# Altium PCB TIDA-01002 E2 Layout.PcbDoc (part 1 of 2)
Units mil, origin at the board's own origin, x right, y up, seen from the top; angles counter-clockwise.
Board outline 1055.12 x 1877.5 mil, 6 copper layers (Layer 1 - Top Layer, Layer 2 - GND, Layer 3 - Signal, Layer 4 - Signal 2, Layer 5 - GND, Layer 6 - Bottom Layer), stack 61.268 mil thick; 83 components, 52 nets, 333 pads, 146 vias.
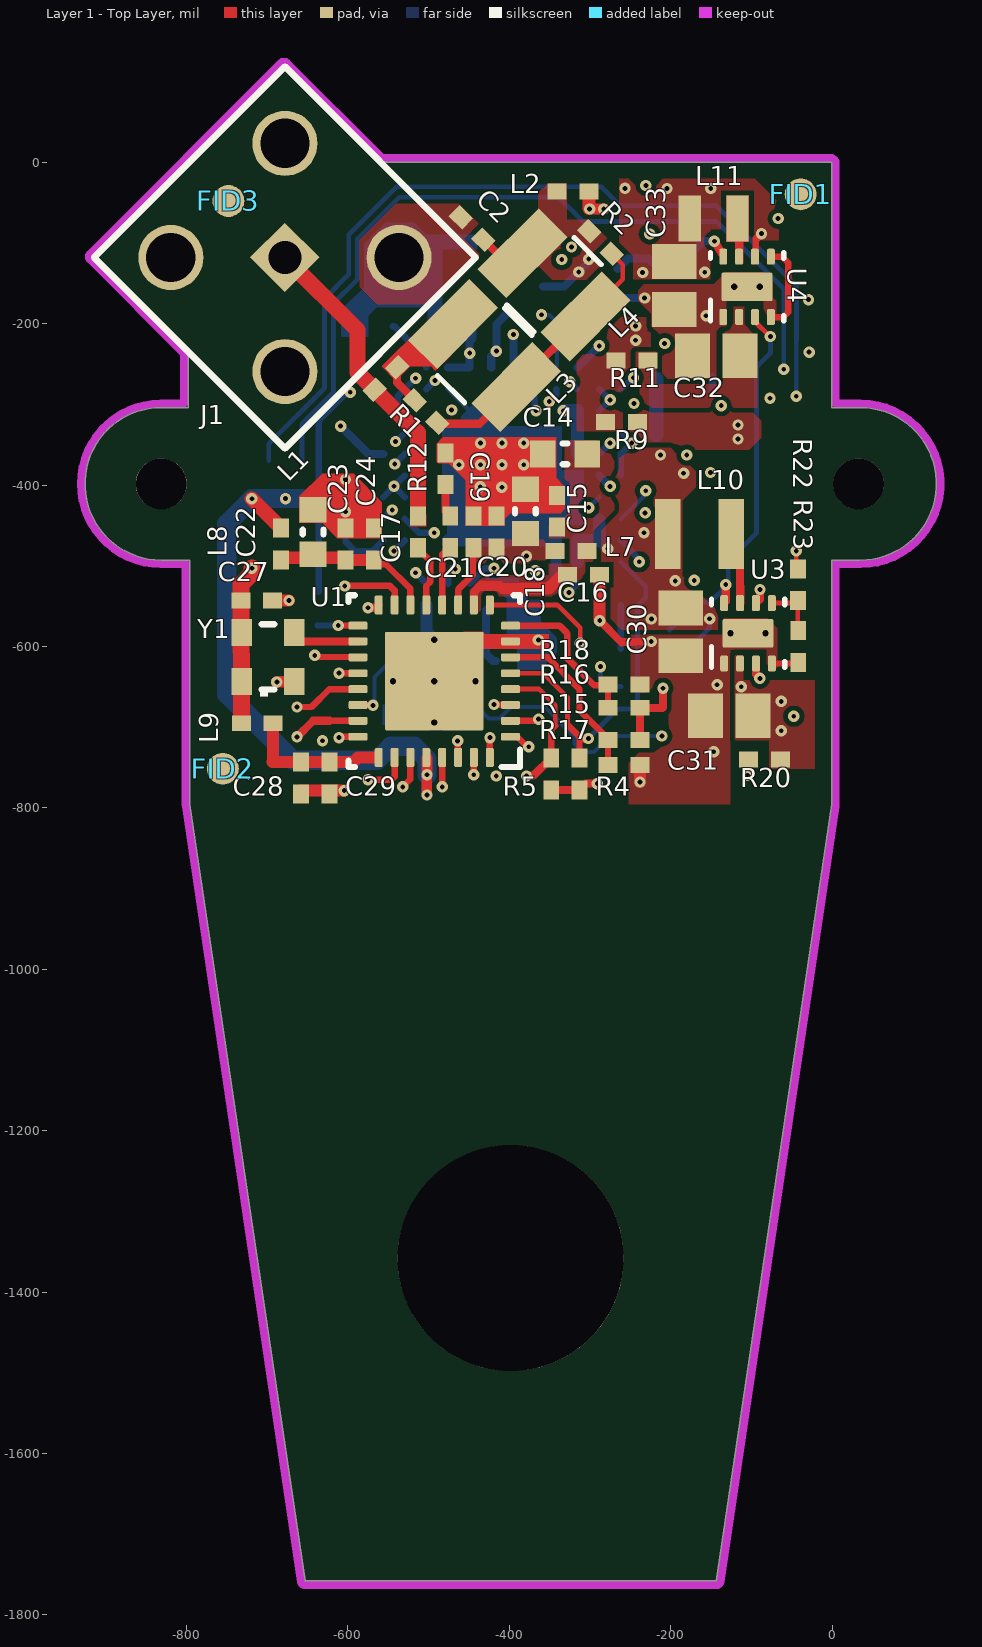
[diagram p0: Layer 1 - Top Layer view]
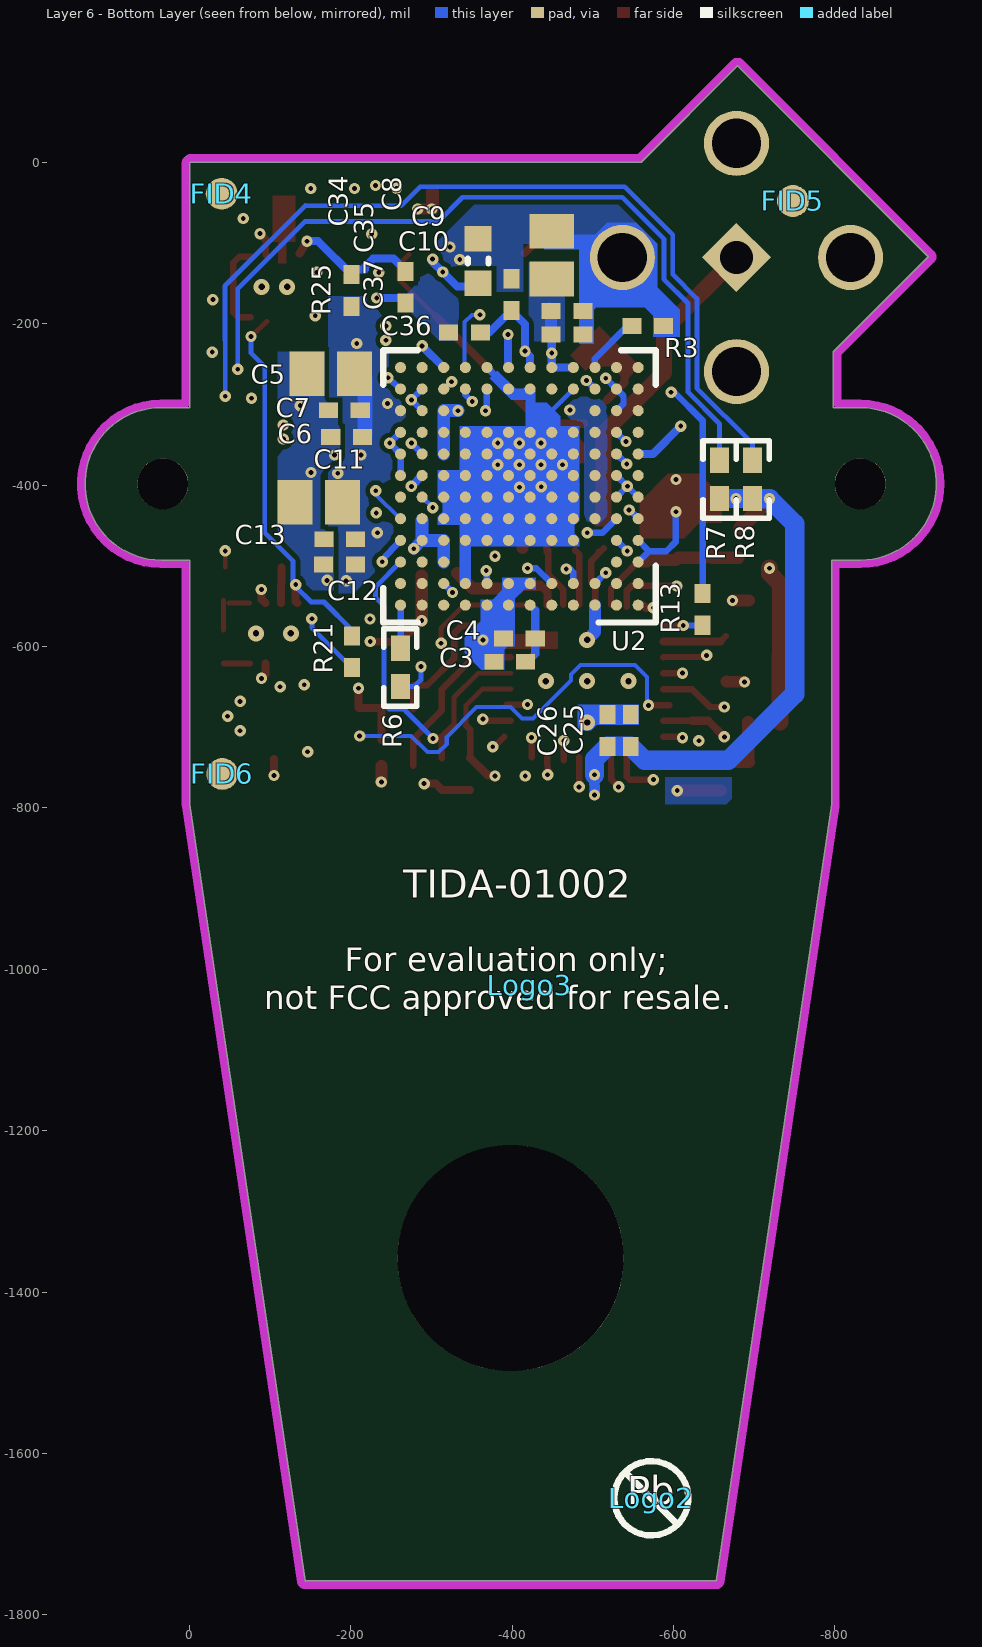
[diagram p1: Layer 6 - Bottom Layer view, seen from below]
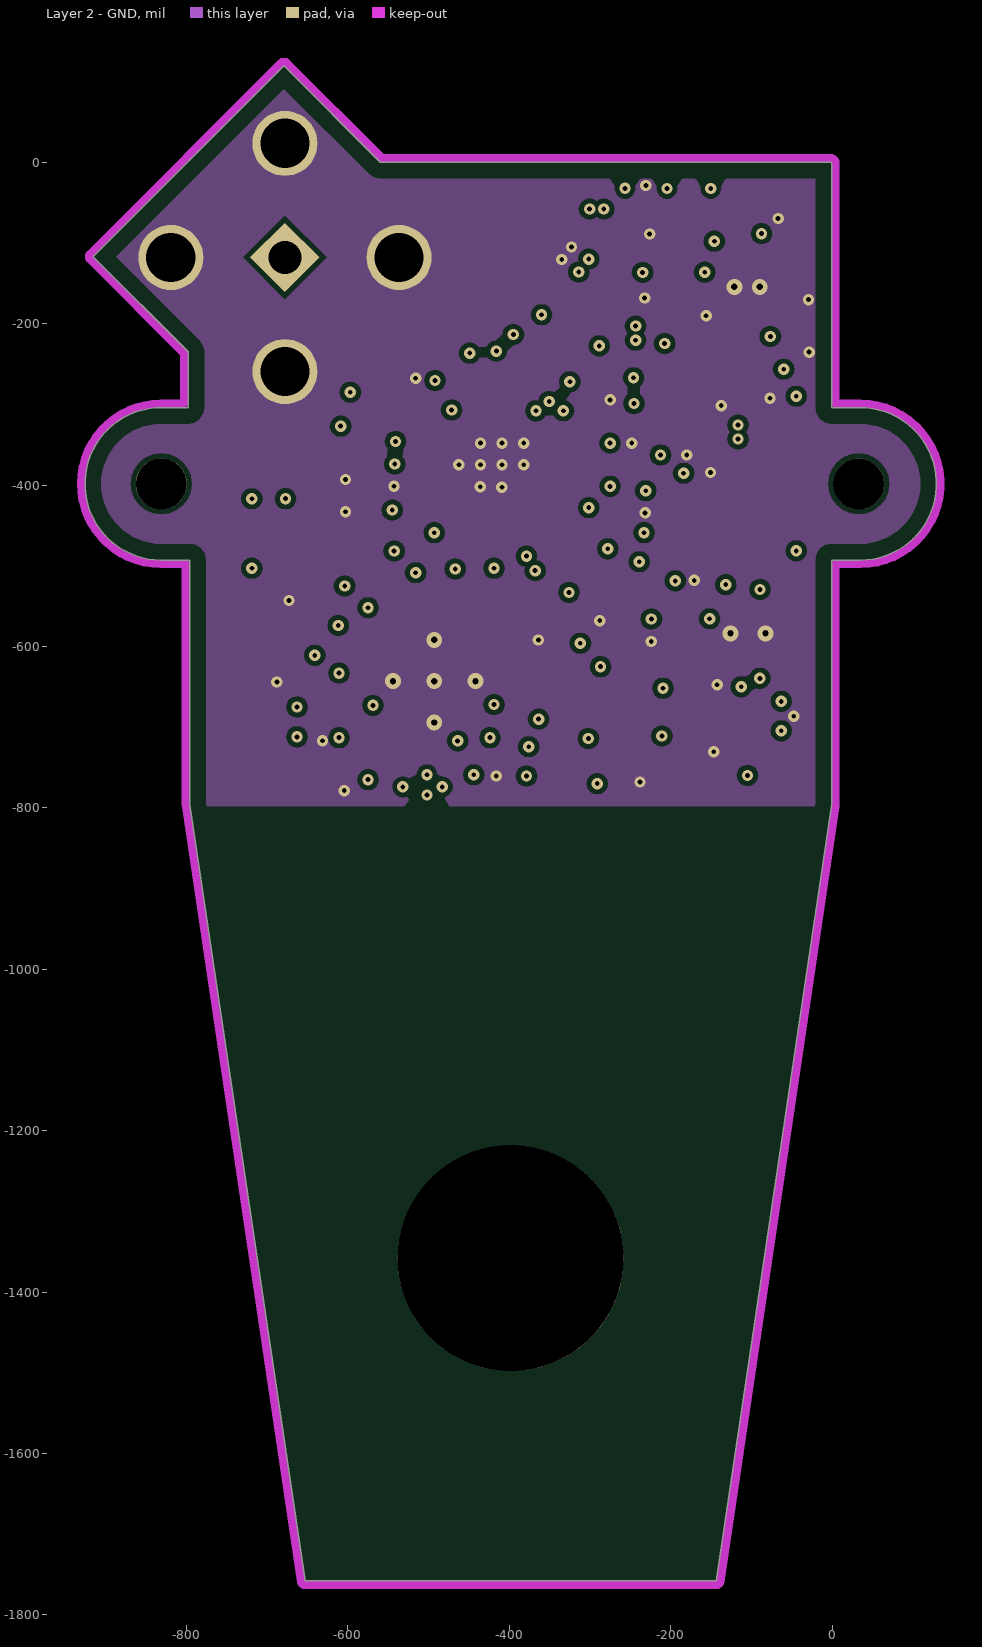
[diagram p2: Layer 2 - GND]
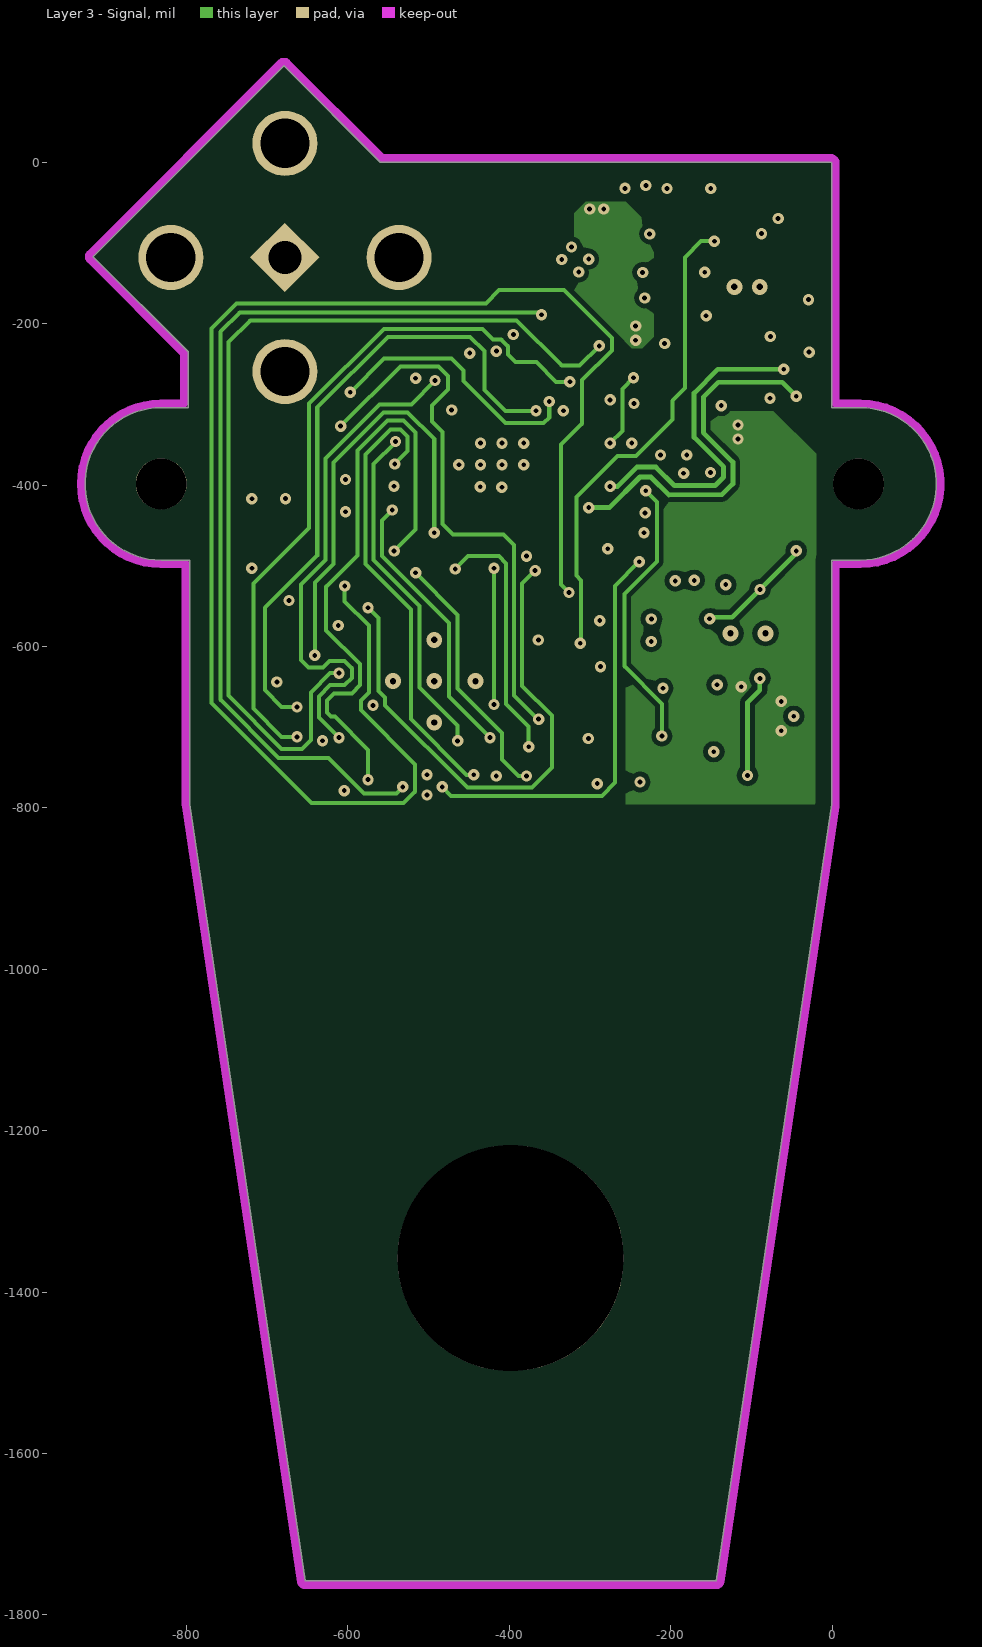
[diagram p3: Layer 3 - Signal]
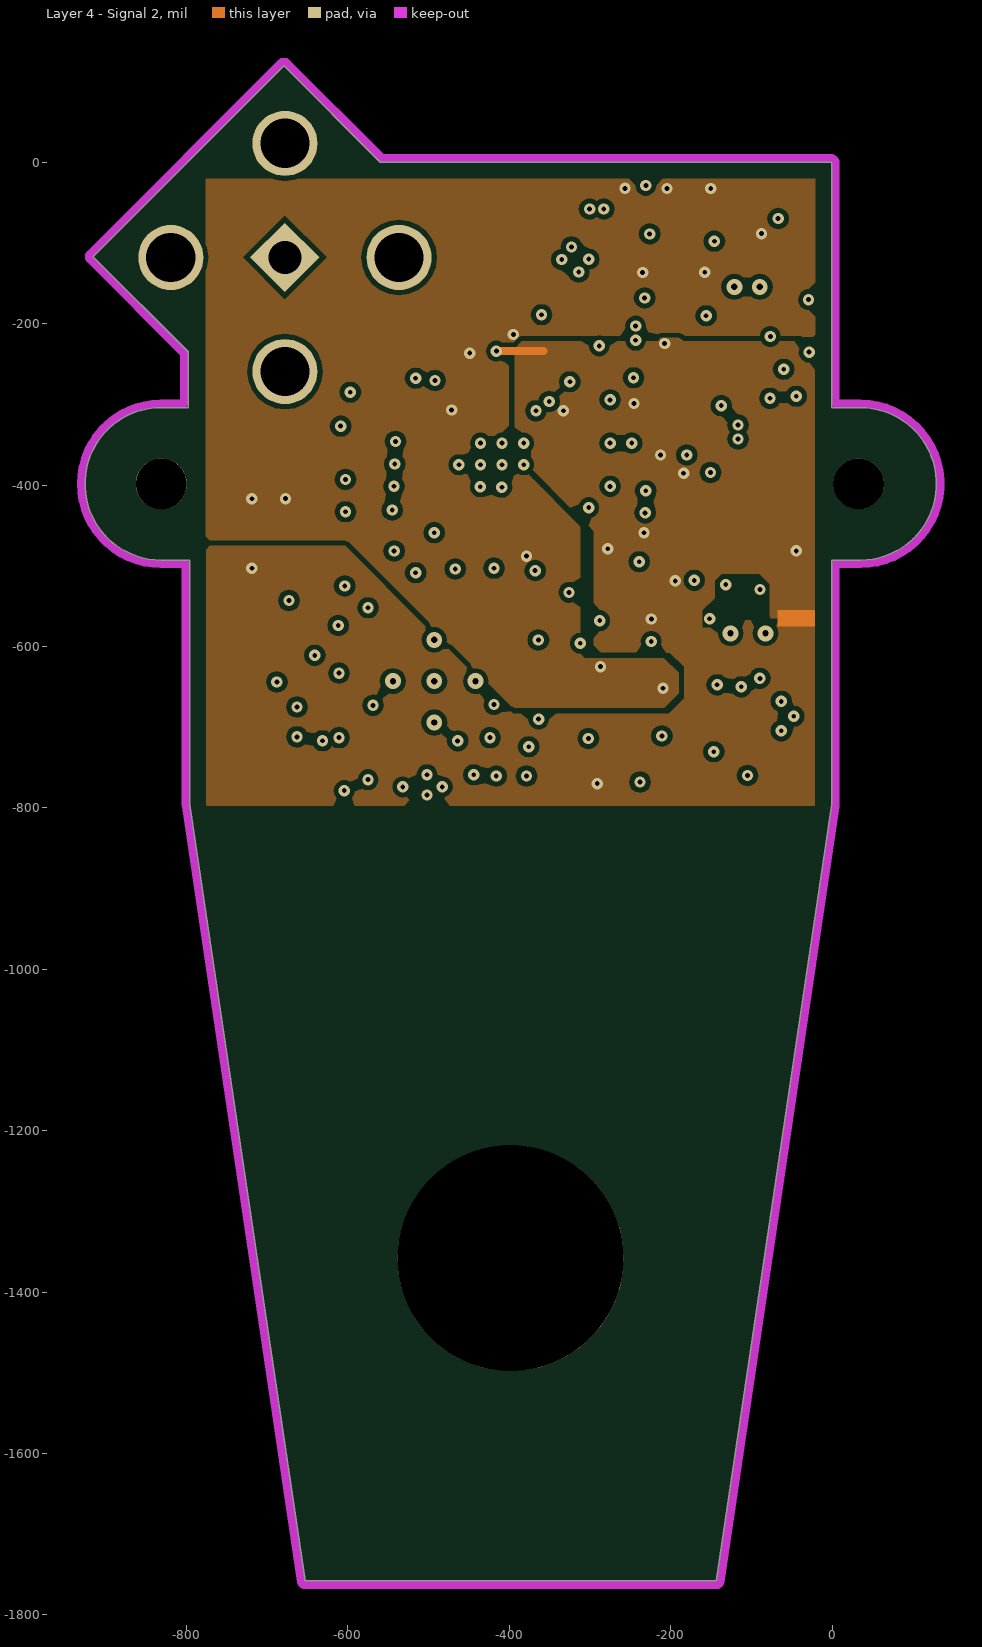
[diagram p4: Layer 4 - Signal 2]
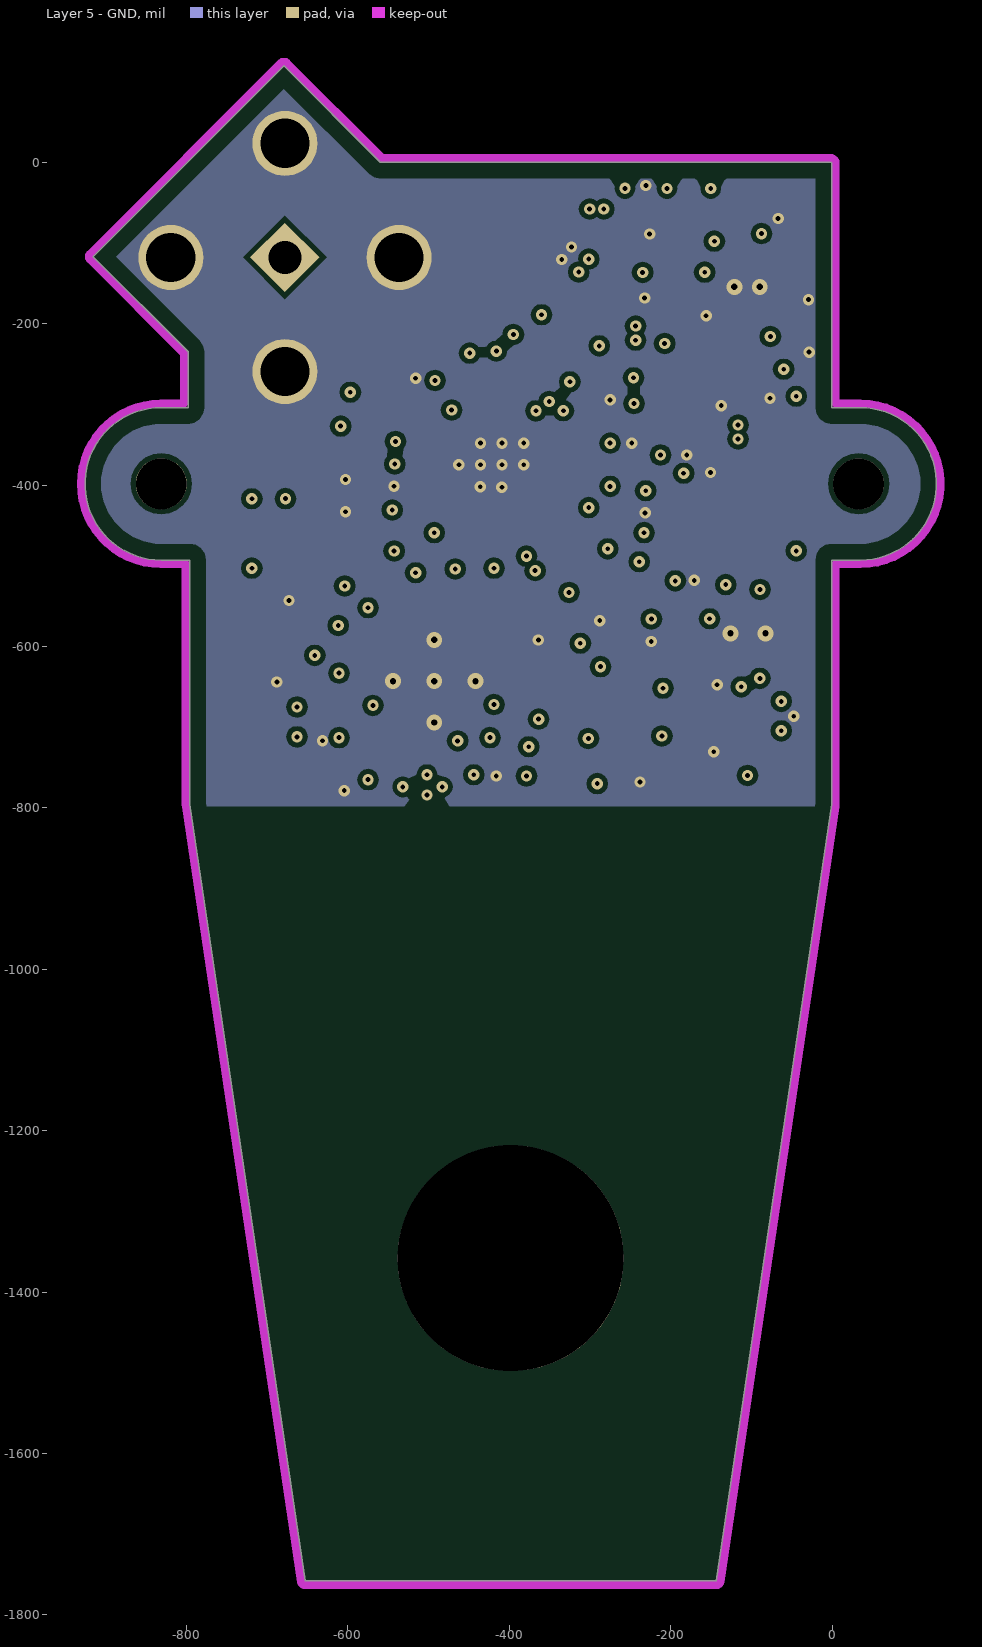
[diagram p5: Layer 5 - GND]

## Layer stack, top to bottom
Top Solder: solder mask 0.4, Solder Resist, Dk 3.5
Layer 1 - Top Layer: signal copper 1.4
Dielectric 1: core 10.6, 370HR, Dk 4.2
Layer 2 - GND: signal copper 1.417
Dielectric 6: prepreg 8, 370HR, Dk 4.2
Layer 3 - Signal: signal copper 1.417
Dielectric 3: core 15.6, 370HR, Dk 4.2
Layer 4 - Signal 2: signal copper 1.417
Dielectric 4: prepreg 8, 370HR, Dk 4.2
Layer 5 - GND: signal copper 1.417
Dielectric 5: core 10.6, 370HR, Dk 4.2
Layer 6 - Bottom Layer: signal copper 1.4
Bottom Solder: solder mask 0.4, Solder Resist, Dk 3.5

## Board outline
-831.32,-492.99 -795.89,-492.99 -795.89,-796.14 -795.89,-795.5 -653,-1758 -143.5,-1758 -0.61,-795.5 -0.61,-796.14 -0.61,-492.99 34.82,-492.99 ccw(c34.82,-398.5) 34.82,-304.01 -0.61,-304.01 -0.61,-0.86 -1.61,0.13 -559.88,0.13 -679.25,119.5 -915.75,-117 -797.88,-234.87 -797.88,-304.01 -831.32,-304.01 ccw(c-831.32,-398.5)

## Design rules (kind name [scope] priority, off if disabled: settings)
AcuteAngle [All] p1: minimum=4.50000000000000E+0001 checktracksonly=FALSE
AssemblyTestPointUsage [All] p1: valid=2
BoardOutlineClearance BoardOutlineClearance_MountingHoles [OnCopper and InComponentClass('Mounting Holes')] p1: gap=40 ignorepadtopadclearanceinfootprint=FALSE
BoardOutlineClearance BoardOutlineClearance_Poly [OnCopper and InPoly] p2: gap=19 ignorepadtopadclearanceinfootprint=FALSE
BoardOutlineClearance [OnCopper and Not InComponentClass('Logo') and not InComponentClass('FiducialMark') and not InRegion(1000,500,4000,800)] p3: gap=20 ignorepadtopadclearanceinfootprint=FALSE
Clearance Clearance_Keepouts [((IsTrack Or IsArc) And Not InPoly) And IsFree and IsKeepOut vs ((IsTrack Or IsArc) And Not InPoly) And IsFree and IsKeepOut] p1: gap=5 ignorepadtopadclearanceinfootprint=FALSE except(0: Arc-Hole Track-Hole SMDPad-Hole THPad-Hole Via-Hole Fill-Hole Poly-Hole Region-Hole Text-Hole)
Clearance Clearance_Poly [InPolygon] p2: gap=6 ignorepadtopadclearanceinfootprint=FALSE except(0: Arc-Hole Track-Hole SMDPad-Hole THPad-Hole Via-Hole Fill-Hole Poly-Hole Region-Hole Text-Hole)
Clearance [All] p3: gap=5 ignorepadtopadclearanceinfootprint=FALSE except(0: Arc-Hole Track-Hole SMDPad-Hole THPad-Hole Via-Hole Fill-Hole Poly-Hole Region-Hole Text-Hole)
ComponentClearance ComponentClearance_U4-FID1 [InComponent('U4') vs InComponent('FID1')] p1: gap=0 collisioncheckmode=3 verticalgap=0 showdistances=FALSE
ComponentClearance ComponentClearance_J1-FID3 [InComponent('J1') vs InComponent('FID3')] p2: gap=0 collisioncheckmode=3 verticalgap=0 showdistances=FALSE
ComponentClearance ComponentClearance_MountingHoles_FiducialMarks [InComponentClass('Mounting Holes') vs InComponentClass('FiducialMark')] p3: gap=5 collisioncheckmode=3 verticalgap=10 showdistances=FALSE
ComponentClearance ComponentClearance_Shunt [InComponentClass('Header') vs InComponentClass('Shunt')] p4: gap=0 collisioncheckmode=3 verticalgap=0 showdistances=FALSE
ComponentClearance ComponentClearance_Logo [InComponentClass('Logo')] p5: gap=5 collisioncheckmode=3 verticalgap=10 showdistances=FALSE
ComponentClearance ComponentClearance_ScrewToNut [(HasFootprint('NY PMS 440 0025 PH')) vs (HasFootprint('Keystone_1902C'))] p6: gap=5 collisioncheckmode=3 verticalgap=10 showdistances=FALSE
ComponentClearance ComponentClearance_MountingHoles [InComponentClass('Mounting Holes')] p7: gap=5 collisioncheckmode=3 verticalgap=100000 showdistances=FALSE
ComponentClearance ComponentClearance_SmallPassives [HasFootprint('0201*') or HasFootprint('0402*') or HasFootprint('0508') or HasFootprint('0603*') or HasFootprint('0612') or HasFootprint('0805*') or HasFootprint('0815*') or HasFootprint('0830*') or HasFootprint('1206*') or HasFootprint('1210*') or HasFootprint('1808*') or HasFootprint('1812*') or HasFootprint('1825*') or HasFootprint('2010*') or HasFootprint('2220*') or HasFootprint('2225*') or HasFootprint('2512*') or HasFootprint('2728*') or HasFootprint('3518*') vs HasFootprint('0201*') or HasFootprint('0402*') or HasFootprint('0508') or HasFootprint('0603*') or HasFootprint('0612') or HasFootprint('0805*') or HasFootprint('0815*') or HasFootprint('0830*') or HasFootprint('1206*') or HasFootprint('1210*') or HasFootprint('1808*') or HasFootprint('1812*') or HasFootprint('1825*') or HasFootprint('2010*') or HasFootprint('2220*') or HasFootprint('2225*') or HasFootprint('2512*') or HasFootprint('2728*') or HasFootprint('3518*')] p8: gap=5 collisioncheckmode=3 verticalgap=10 showdistances=FALSE
ComponentClearance ComponentClearance_THtoSMT [IsThruComponent vs IsSMTComponent] p9: gap=5 collisioncheckmode=3 verticalgap=30 showdistances=FALSE
ComponentClearance ComponentClearance_THtoTH [IsThruComponent vs IsThruComponent] p10: gap=5 collisioncheckmode=3 verticalgap=30 showdistances=FALSE
ComponentClearance [All] p11: gap=5 collisioncheckmode=3 verticalgap=10 showdistances=FALSE
DiffPairsRouting [All] p1: maxlimit=100 minlimit=10 mostfreqgap=10 toplayer_minwidth=15 toplayer_maxwidth=15 toplayer_prefwidth=15 midlayer1_minwidth=15 midlayer1_maxwidth=15 midlayer1_prefwidth=15 midlayer2_minwidth=15 midlayer2_maxwidth=15 midlayer2_prefwidth=15 midlayer3_minwidth=15 midlayer3_maxwidth=15 midlayer3_prefwidth=15 midlayer4_minwidth=15 midlayer4_maxwidth=15 midlayer4_prefwidth=15 bottomlayer_minwidth=15 bottomlayer_maxwidth=15 bottomlayer_prefwidth=15 maxuncoupledlength=1000
FabricationTestPointUsage TestPointUsage [All] p1: valid=2 allowmultiple=FALSE
FabricationTestpoint Testpoint [All] p1: side=3 testpointundercomponent=TRUE minsize=40 maxsize=100 preferedsize=60 minholesize=0 maxholesize=40 preferedholesize=32 testpointgrid=1 allowsidetop=TRUE allowsidebottom=TRUE usegrid=TRUE gridtolerance=0.01
FanoutControl Fanout_LCC [IsLCC] p1: bgadir=Out bgaviamode=Centered fanoutstyle=Auto fanoutdirection=Alternating viagrid=1 // Fanout_LCC (Default Rule)
FanoutControl Fanout_BGA [IsBGA] p2: bgadir=Out bgaviamode=Centered fanoutstyle=Auto fanoutdirection=Alternating viagrid=1 // Fanout_BGA (Default Rule)
FanoutControl Fanout_Default [All] p4: bgadir=Out bgaviamode=Centered fanoutstyle=Auto fanoutdirection=Alternating viagrid=1 // Fanout_Default (Default Rule)
FanoutControl Fanout_Small [(CompPinCount < 5)] p5: bgadir=Out bgaviamode=Centered fanoutstyle=Auto fanoutdirection=OutThenIn viagrid=1 // Fanout_Small (Default Rule)
HoleSize [All] p1: absolutevalues=TRUE maxlimit=280 minlimit=6 maxpercent=80.000 minpercent=20.000
MinimumAnnularRing MinimumAnnularRing_ThermalPadVias [IsVia and InAnyComponent] p1: minimumring=5.91
MinimumAnnularRing [All] p2: minimumring=4
MinimumSolderMaskSliver MinimumSolderMaskSliver_Logo [InComponentClass('Logo') vs InComponentClass('Logo')] p1: minsoldermaskwidth=0.7
MinimumSolderMaskSliver [All] p2: minsoldermaskwidth=3.94
PlaneConnect [All] p1: planeconnectstyle=Relief reliefexpansion=10 reliefentries=4 reliefconductorwidth=10 reliefairgap=10
PolygonConnect [All] p1: connectstyle=Direct reliefconductorwidth=10 reliefentries=4 polygonreliefangle="90 Angle" airgapwidth=10
RoutingVias ThermalPadVias [IsVia and InAnyComponent] p1: holewidth=7.87 width=19.68 viastyle="Through Hole" minholewidth=7.87 minwidth=19.68 maxholewidth=12.99 maxwidth=23.62
RoutingVias [All] p2: holewidth=16 width=34 viastyle="Through Hole" minholewidth=6 minwidth=14 maxholewidth=40 maxwidth=65
SilkToBoardRegionClearance [Not ((IsComment or IsDesignator) And (Hide <> 'False')) and not InRegion(1000,500,4000,800)] p1:
SilkToSilkClearance SilkToSilkClearance_Pb-FreeLogo [(HasFootprint('Pb-Free_Overlay_Medium') OR HasFootprint('Pb-Free_Overlay_Small')) vs (HasFootprint('Pb-Free_Overlay_Medium') OR HasFootprint('Pb-Free_Overlay_Small'))] p1: silktosilkclearance=0
SilkToSilkClearance [All] p2: silktosilkclearance=3
SilkToSolderMaskClearance SilkToComponentPadClearance [IsPad and InAnycomponent] p1: minsilkscreentomaskgap=3 clearancetoexposedcopper=TRUE
SilkToSolderMaskClearance "Silk to Solder Mask Opening" [All] p2: minsilkscreentomaskgap=3 clearancetoexposedcopper=FALSE
SolderMaskExpansion [All] p1: expansion=1.97
Width [All] p1: maxlimit=100 minlimit=5 preferedwidth=10 checkconnectedcopper=TRUE
15 further rules are at their usual default settings.

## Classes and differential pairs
component class Serializer: C14 C15 C16 C17 C18 C19 C20 C21 C22 C23 C24 C25 C26 C27 C28 C29 C37 L7 L8 L9 R12 R13 R15 R16 R17 R18 R25 U1 Y1
component class "Power over Coax Filter & Power Supply": C2 C30 C31 C32 C33 C34 J1 L1 L2 L3 L4 L10 L11 R1 R2 R9 R11 R20 R21 R22 R23 U3 U4
component class "ON Semiconductor AS0140AT Imager + ISP": C3 C4 C5 C6 C7 C8 C9 C10 C11 C12 C13 C35 C36 R3 R4 R5 R6 R7 R8 U2
component class AssemblyNote: ZZ1 ZZ2 ZZ3
component class FiducialMark: FID1 FID2 FID3 FID4 FID5 FID6
component class TID_Hardware: FID1 FID2 FID3 FID4 FID5 FID6 Logo2 Logo3 ZZ1 ZZ2 ZZ3

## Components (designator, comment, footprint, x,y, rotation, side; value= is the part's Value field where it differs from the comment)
C2 "C1005X7R1E104K050BB" 0402L -446,-82 r135 top value=0.1µF
C3 "GRM155R61A105KE15D" 0402L -397,-619 r0 bottom value=1uF
C4 "GRM155R71C104KA88D" 0402L -409,-590 r0 bottom value=0.1uF
C5 "GRM21BR71A106KE51L" 0805L -175.3,-261.9 r0 bottom value=10uF
C6 "C1005X7R1E104K050BB" 0402L -194.9,-340.3 r0 bottom value=0.1µF
C7 "GRM155R71C103KA01D" 0402L -192.1,-307.3 r0 bottom value=0.01uF
C8 "GRM21BR71A106KE51L" 0805L -449,-115 r90 bottom value=10uF
C9 "C1005X7R1E104K050BB" 0402L -468,-184.5 r180 bottom value=0.1µF
C10 "GRM155R71C103KA01D" 0402L -468,-213.5 r180 bottom value=0.01uF
C11 "GRM21BR71A106KE51L" 0805L -160.3,-421.1 r0 bottom value=10uF
C12 "GRM155R61A105KE15D" 0402L -186.1,-498.2 r0 bottom value=1uF
C13 "GRM155R71C103KA01D" 0402L -186.4,-467.1 r0 bottom value=0.01uF
C14 "JMK107BB7475MA-T" 0603L -331,-361.26 r180 top value=4.7uF
C15 "GRM155R71C104KA88D" 0402L -341,-432.5 r90 top value=0.1uF
C16 "GRM155R71C103KA01D" 0402L -308,-511.1 r0 top value=0.01uF
C17 "C1005X7R1H104K" 0402L -513,-458 r270 top value=0.1uF
C18 "CL10B475KQ8NQNC" 0603L -380.1,-432.5 r90 top value=4.7µF
C19 "GRM155R71C104KA88D" 0402L -444.6,-458 r90 top value=0.1uF
C20 "GRM155R71C103KA01D" 0402L -416,-458.1 r90 top value=0.01uF
C21 "C1005X7R1H104K" 0402L -473.2,-458 r270 top value=0.1uF
C22 "CL10B475KQ8NQNC" 0603L -643,-458 r90 top value=4.7µF
C23 "GRM155R71C104KA88D" 0402L -603,-473 r90 top value=0.1uF
C24 "GRM155R71C103KA01D" 0402L -568,-473 r90 top value=0.01uF
C25 "GRM155R71C104KA88D" 0402L -547,-704 r90 bottom value=0.1uF
C26 "GRM155R71C103KA01D" 0402L -518,-704 r90 bottom value=0.01uF
C27 "GRM155R71C104KA88D" 0402L -713,-543 r0 top value=0.1uF
C28 "GRM155R71C104KA88D" 0402L -658,-763 r270 top value=0.1uF
C29 "GRM155R71C103KA01D" 0402L -623,-763 r270 top value=0.01uF
C30 "GRM21BR71A106KE51L" 0805L -187.4,-582 r270 top value=10uF
C31 "CL21B106KOQNNNE" 0805L -127.5,-686 r180 top value=10uF
C32 "CL21B106KOQNNNE" 0805L -143.73,-240.03 r180 top value=10uF
C33 "GRM21BR71A106KE51L" 0805L -195.6,-152.7 r270 top value=10uF
C34 "GRM188Z71C475KE21D" 0603L -358,-122.5 r90 bottom value=4.7uF
C35 "GRM155R61A105KE15D" 0402L -399,-164 r90 bottom value=1uF
C36 "C1005X7R1E104K050BB" 0402L -341,-211 r0 bottom value=0.1µF
C37 "GRM155R71C104KA88D" 0402L -268.1,-154.9 r270 bottom value=0.1uF
FID1 "Fiducial" Fiducial10-20 -39.1,-39.8 r180 top
FID2 "Fiducial" Fiducial10-20 -754.9,-751.4 r0 top
FID3 "Fiducial" Fiducial10-20 -748,-48 r0 top
FID4 "Fiducial" Fiducial10-20 -40,-39 r0 bottom
FID5 "Fiducial" Fiducial10-20 -748,-48 r0 bottom
FID6 "Fiducial" Fiducial10-20 -41,-758 r0 bottom
J1 "59S10H-40ML5-Z" Rosenberger_59S10H-40ML5-Z -678,-118 r225 top locked
L1 "BLM15AX102SN1D" 0402L -553,-268 r45 top value="1000 ohm"
L2 "BLM15AX102SN1D" 0402L -321,-36 r0 top value="1000 ohm"
L3 "CBC3225T4R7MR" CBC3225 -430.5,-239.5 r315 top value=4.7uH
L4 "CBC3225T101MR" CBC3225 -344.6,-151.8 r135 top value=100uH
L7 "BLM15AX102SN1D" 0402L -323.5,-481.9 r0 top value="1000 ohm"
L8 "BLM15AX102SN1D" 0402L -683,-473 r270 top value="1000 ohm"
L9 "BLM15AX102SN1D" 0402L -712.3,-695.1 r0 top value="1000 ohm"
L10 "74479887310A" WE-PMI_1008 -164.5,-460.5 r180 top value=10uH
L11 "74479775222" WE-PMI-0805_1 -146.9,-69.9 r180 top value=2.2uH
Logo2 "Pb-Free Symbol" Pb-Free_Overlay_Small -572.5,-1655.5 r180 bottom
Logo3 "FCC disclaimer" FCC_disclaimer_stacked -422,-1019.5 r180 bottom
R1 "CRCW04022K00FKED" 0402L -503,-309 r135 top value=2.00k
R2 "CRCW04022K00FKED" 0402L -287,-99.5 r315 top value=2.00k
R3 "CRCW040210K0JNED" 0402L -568,-203 r0 bottom value=10k
R4 "CRCW04023K30JNED" 0402L -313,-758 r270 top value=3.3k
R5 "CRCW04023K30JNED" 0402L -348,-758 r270 top value=3.3k
R6 "CRCW040210K0JNED" 0402 -261.5,-626 r270 bottom value=10k
R7 "CRCW04023K30JNED" 0402 -657,-393 r270 bottom value=3.3k
R8 "CRCW04023K30JNED" 0402 -698,-393 r270 bottom value=3.3k
R9 "CRCW04020000Z0ED" 0402L -261,-322 r180 top value=0
R11 "CRCW04020000Z0ED" 0402L -248,-245.5 r180 top value=0
R12 "CRCW040249R9FKED" 0402L -479,-379.8 r90 top value=49.9
R13 "CRCW040233R0JNED" 0402L -636,-554 r90 bottom value=33
R15 "CRCW040210K0JNED" 0402L -258,-716 r0 top value=10k
R16 "CRCW040210K0JNED" 0402L -258,-676 r0 top value=10k
R17 "CRCW04020000Z0ED" 0402L -258,-747 r180 top value=0
R18 "CRG0402F4K7" 0402L -258,-647 r180 top value=4.70k
R20 "CRCW040210K0JNED" 0402L -83.7,-740.2 r180 top value=10k
R21 "CRCW0402100KFKED" 0402L -201.5,-606.5 r270 bottom value=100k
R22 "CRCW040282K5FKED" 0402L -42.5,-523.5 r90 top value=82.5k
R23 "CRCW040233K2FKED" 0402L -42,-600 r90 top value=33.2k
R25 "CRCW0402100KFKED" 0402L -200.9,-158.8 r270 bottom value=100k
U1 "DS90UB913ATRTVTQ1" RTV0032A -493,-643 r180 top locked
U2 "ON Semiconductor AS0140AT" BGA130_850x850x162 -408.96,-401.54 r0 bottom locked
U3 "TPS62170QDSGRQ1" DSG0008A#1 -104.2,-583.7 r90 top
U4 "TPS62171QDSGRQ1" DSG0008A#2 -105.4,-154.4 r90 top
Y1 "ASDMB-48.000MHZ-LY-T" Abracon_ASDMB -699,-613 r90 top
ZZ1 "These assemblies are ESD sensitive, ESD precautions shall be observed." AssemblyNote -738,2071.11 r0 top
ZZ2 "These assemblies must be clean and free from flux and all contaminants. Use of no clean flux is not acceptable." AssemblyNote -738,1982.56 r0 top
ZZ3 "These assemblies must comply with workmanship standards IPC-A-610 Class 2, unless otherwise specified." AssemblyNote -738,1894 r0 top

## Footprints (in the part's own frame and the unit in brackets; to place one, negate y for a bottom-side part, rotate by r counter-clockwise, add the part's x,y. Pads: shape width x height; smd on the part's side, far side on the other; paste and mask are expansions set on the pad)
0402 [mm] "0402 from SM-752 data"
  rect 0.8x0.6 smd: 1(-0.6,0) 2(0.6,0)
  silkscreen extent -1.22,-0.52 1.22,0.52, body extent -0.55,-0.3 0.55,0.3, height 0.6
0402L [mm] "0402 from SM-752 data"
  rect 0.6x0.5 smd: 1(-0.5,0) 2(0.5,0)
  body extent -0.55,-0.3 0.55,0.3, height 0.6
0603L [mm] "0603 from SM-752 data"
  rect 0.8x0.85 smd: 1(-0.7,0) 2(0.7,0)
  silkscreen extent -0.07,-0.33 0.07,0.33, body extent -0.87,-0.47 0.87,0.47, height 1
0805L [mm] "0805 from SM-752 data"
  rect 1.1x1.4 smd: 1(-0.75,0) 2(0.75,0)
  body extent -1.1,-0.72 1.1,0.72, height 1.45
Abracon_ASDMB [mm] "SMD, 4-Leads, Body 2.5x2mm"
  rect 0.85x0.65 smd: 1(-0.775,0.825) 2(-0.775,-0.825) 3(0.775,-0.825) 4(0.775,0.825)
  silkscreen extent -1.25,-0.2 1.02,0.25, body extent -1.02,-1.27 1.02,1.28, height 0.91
AssemblyNote [mil] "Assembly Note"
BGA130_850x850x162 [mm] "BGA, 130-Balls, Body 8.5x8.5mmx1.62mm, Pitch 0.68mm"
  round 0.35 smd: A1(-3.74,3.74) A2(-3.06,3.74) A3(-2.38,3.74) A4(-1.7,3.74) A5(-1.02,3.74) A6(-0.34,3.74) A7(0.34,3.74) A8(1.02,3.74) A9(1.7,3.74) A10(2.38,3.74) A11(3.06,3.74) A12(3.74,3.74) B1(-3.74,3.06) B2(-3.06,3.06) B3(-2.38,3.06) B4(-1.7,3.06) B5(-1.02,3.06) B6(-0.34,3.06) B7(0.34,3.06) B8(1.02,3.06) B9(1.7,3.06) B10(2.38,3.06) B11(3.06,3.06) B12(3.74,3.06) C1(-3.74,2.38) C2(-3.06,2.38) C10(2.38,2.38) C11(3.06,2.38) C12(3.74,2.38) D1(-3.74,1.7) D2(-3.06,1.7) D4(-1.7,1.7) D5(-1.02,1.7) D6(-0.34,1.7) D7(0.34,1.7) D8(1.02,1.7) D9(1.7,1.7) D10(2.38,1.7) D11(3.06,1.7) D12(3.74,1.7) E1(-3.74,1.02) E2(-3.06,1.02) E3(-2.38,1.02) E4(-1.7,1.02) E5(-1.02,1.02) E6(-0.34,1.02) E7(0.34,1.02) E8(1.02,1.02) E9(1.7,1.02) E10(2.38,1.02) E11(3.06,1.02) E12(3.74,1.02) F1(-3.74,0.34) F2(-3.06,0.34) F3(-2.38,0.34) F4(-1.7,0.34) F5(-1.02,0.34) F6(-0.34,0.34) F7(0.34,0.34) F8(1.02,0.34) F9(1.7,0.34) F10(2.38,0.34) F11(3.06,0.34) F12(3.74,0.34) G1(-3.74,-0.34) G2(-3.06,-0.34) G3(-2.38,-0.34) G4(-1.7,-0.34) G5(-1.02,-0.34) G6(-0.34,-0.34) G7(0.34,-0.34) G8(1.02,-0.34) G9(1.7,-0.34) G10(2.38,-0.34) G11(3.06,-0.34) G12(3.74,-0.34) H1(-3.74,-1.02) H2(-3.06,-1.02) H3(-2.38,-1.02) H4(-1.7,-1.02) H5(-1.02,-1.02) H6(-0.34,-1.02) H7(0.34,-1.02) H8(1.02,-1.02) H9(1.7,-1.02) H10(2.38,-1.02) H11(3.06,-1.02) H12(3.74,-1.02) J1(-3.74,-1.7) J2(-3.06,-1.7) J3(-2.38,-1.7) J4(-1.7,-1.7) J5(-1.02,-1.7) J6(-0.34,-1.7) J7(0.34,-1.7) J8(1.02,-1.7) J9(1.7,-1.7) J10(2.38,-1.7) J11(3.06,-1.7) J12(3.74,-1.7) K1(-3.74,-2.38) K2(-3.06,-2.38) K3(-2.38,-2.38) K10(2.38,-2.38) K11(3.06,-2.38) K12(3.74,-2.38) L1(-3.74,-3.06) L2(-3.06,-3.06) L3(-2.38,-3.06) L4(-1.7,-3.06) L5(-1.02,-3.06) L6(-0.34,-3.06) L7(0.34,-3.06) L8(1.02,-3.06) L9(1.7,-3.06) L10(2.38,-3.06) L11(3.06,-3.06) L12(3.74,-3.06) M1(-3.74,-3.74) M2(-3.06,-3.74) M3(-2.38,-3.74) M4(-1.7,-3.74) M5(-1.02,-3.74) M6(-0.34,-3.74) M7(0.34,-3.74) M8(1.02,-3.74) M9(1.7,-3.74) M10(2.38,-3.74) M11(3.06,-3.74) M12(3.74,-3.74)
  silkscreen extent -4.29,-4.29 4.29,4.29, body extent -4.34,-4.34 4.34,4.34, height 1.62
CBC3225 [mm] "TAIYO YUDEN, IPC nominal footprint."
  rect 1.29x2.72 smd: 1(-1.405,0) 2(1.405,0)
  silkscreen extent -0.6,-1.5 0.6,1.5, body extent -1.7,-1.35 1.7,1.35, height 2.7
DSG0008A#1 [mm] "SON, 8-Leads, Body 2x2mm, Pitch 0.5mm, Thermal Pad 1.6x0.9mm, TI Recommended"
  rrect40% 0.5x0.25 smd: 1(-0.95,0.75) 2(-0.95,0.25) 3(-0.95,-0.25) 4(-0.95,-0.75) 5(0.95,-0.75) 6(0.95,-0.25) 7(0.95,0.25) 8(0.95,0.75)
  rrect14% 0.9x0.7 on Top Paste: 9(0,0.45) 9(0,-0.45)
  rrect11% 0.9x1.6 smd paste-0.45: 9(0,0)
  silkscreen extent -1.07,-1.15 1.07,1.15, body extent -1,-1 1,1, height 0.77
DSG0008A#2 [mm] "SON, 8-Leads, Body 2x2mm, Pitch 0.5mm, Thermal Pad 1.6x0.9mm, TI Recommended"
  rrect40% 0.5x0.25 smd: 1(-0.95,0.75) 2(-0.95,0.25) 3(-0.95,-0.25) 4(-0.95,-0.75) 5(0.95,-0.75) 6(0.95,-0.25) 7(0.95,0.25) 8(0.95,0.75)
  rrect11% 0.9x1.6 smd paste-0.45: 9(0,0)
  silkscreen extent -1.07,-1.15 1.07,1.15, body extent -1.05,-1.05 1.05,1.05, height 0.8
FCC_disclaimer_stacked [mil]
Fiducial10-20 [mm]
  round 1 smd mask+0.5: 1(0,0)
Pb-Free_Overlay_Small [mil]
  silkscreen extent -46,-46 46,46
Rosenberger_59S10H-40ML5-Z [mm] "Connector, HF, TH"
  rect 1.55x1.55 hole 1.05: 1(0,0)
  round 2.05 hole 1.55: 2(-2.54,2.54) 3(2.54,2.54) 4(2.54,-2.54) 5(-2.54,-2.54)
  silkscreen extent -4.25,-4.25 4.25,4.25, body extent -4.25,-5.75 4.25,4.25, height 12.45
RTV0032A [mm] "QFN, 32-Leads, Body 5x5mm, Pitch 0.5mm"
  rrect40% 0.6x0.25 smd: 1(-2.4,1.75) 2(-2.4,1.25) 3(-2.4,0.75) 4(-2.4,0.25) 5(-2.4,-0.25) 6(-2.4,-0.75) 7(-2.4,-1.25) 8(-2.4,-1.75) 17(2.4,-1.75) 18(2.4,-1.25) 19(2.4,-0.75) 20(2.4,-0.25) 21(2.4,0.25) 22(2.4,0.75) 23(2.4,1.25) 24(2.4,1.75)
  rrect40% 0.25x0.6 smd: 9(-1.75,-2.4) 10(-1.25,-2.4) 11(-0.75,-2.4) 12(-0.25,-2.4) 13(0.25,-2.4) 14(0.75,-2.4) 15(1.25,-2.4) 16(1.75,-2.4) 25(1.75,2.4) 26(1.25,2.4) 27(0.75,2.4) 28(0.25,2.4) 29(-0.25,2.4) 30(-0.75,2.4) 31(-1.25,2.4) 32(-1.75,2.4)
  rrect3% 3.1x3.1 smd paste-1.55: 33(0,0)
  silkscreen extent -2.7,-2.7 2.7,2.7, body extent -2.55,-2.55 2.55,2.55, height 0.81
WE-PMI-0805_1 [mm] "WURTH"
  rect 0.7x1.45 smd: 1(-0.75,0) 2(0.75,0)
  body extent -1.1,-0.7 1.1,0.7, height 1
WE-PMI_1008 [mm] "WURTH"
  rect 0.8x2.2 smd: 1(-1,0) 2(1,0)
  body extent -1.35,-1.1 1.35,1.1, height 1

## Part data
C2 C6 C9 C36: library part C1005X7R1E103K, "CAP, CERM, 0.1uF, 25V, +/-10%, X7R, 0402", Manufacturer="TDK Corporation", Operating Temperature="-55°C ~ 125°C", Ratings=-, Supplier Part Number 1=445-7348-1-ND, TempCo=X7R, Tolerance_%=±10%
C3 C12 C35: "CAP, CERM, 1 µF, 10 V, +/- 10%, X5R, 0402", Cap_Case=0402, Manufacturer=MuRata, Supplier Part Number 1=490-3890-1-ND, TempCo=X5R, Tolerance_%=10, Value1=Unknown, Value2=10V, ValueDisplayed=1µF
C4 C19 C23 C25 C27 C28 C37: "CAP, CERM, 0.1uF, 16V, +/-10%, X7R, 0402", Cap_Case=0402, Manufacturer=MuRata, Supplier Part Number 1=490-3261-1-ND, TempCo=X7R, Tolerance_%=10, Value1=Unknown, Value2=16V, ValueDisplayed=0.1µF
C5 C8 C11 C30: "CAP, CERM, 10uF, 10V, +/-10%, X7R, 0805", Cap_Case=0805, Manufacturer=MuRata, Supplier Part Number 1=490-3905-1-ND, TempCo=X7R, Tolerance_%=10, Value1="0.003 ohm", Value2=10V, ValueDisplayed=10µF
C7 C10 C13 C16 C20 C24 C26 C29: "CAP, CERM, 0.01uF, 16V, +/-10%, X7R, 0402", Cap_Case=0402, Manufacturer=MuRata, Supplier Part Number 1=490-1313-1-ND, TempCo=X7R, Tolerance_%=10, Value1=Unknown, Value2=16V, ValueDisplayed=0.01µF
C14: "CAP, CERM, 4.7 µF, 6.3 V, +/- 10%, X7R, 0603", Cap_Case=0603, Manufacturer="Taiyo Yuden", TempCo=X7R, Tolerance_%=10, Value1=Unknown, Value2=6.3V, ValueDisplayed=4.7µF
C15: "CAP, CERM, 0.1 µF, 16 V, +/- 10%, X7R, 0402", Cap_Case=0402, Manufacturer=MuRata, Supplier Part Number 1=490-3261-1-ND, TempCo=X7R, Tolerance_%=10, Value1=Unknown, Value2=16V, ValueDisplayed=0.1µF
C17 C21: "CAP, CERM, 0.1uF, 50V, +/-10%, C0G/NP0, 0402", Cap_Case=0402, Manufacturer=TDK, Supplier Part Number 1=445-5932-1-ND, TempCo=C0G/NP0, Tolerance_%=10, Value1=Unknown, Value2=50V, ValueDisplayed=0.1µF
C18 C22: library part Capacitor, "CAP CER 4.7UF 6.3V 10% X7R 0603", Alternate Manufacturer=-, Manufacturer="Samsung Electro-Mechanics America, Inc", Operating Temperature="-55°C ~ 125°C", Supplier Part Number 1=1276-2087-1-ND, TempCo=X7R, Tolerance_%=±10%
C31 C32: "CAP, CERM, 10 µF, 16 V, +/- 10%, X7R, 0805", Cap_Case=0805, Manufacturer="Samsung Electro-Mechanics", TempCo=X7R, Tolerance_%=10, Value1=Unknown, Value2=16V, ValueDisplayed=10µF
C33: "CAP, CERM, 10 µF, 10 V, +/- 10%, X7R, 0805", Cap_Case=0805, Manufacturer=MuRata, Supplier Part Number 1=490-3905-1-ND, TempCo=X7R, Tolerance_%=10, Value1="0.003 ohm", Value2=10V, ValueDisplayed=10µF
C34: "CAP, CERM, 4.7 µF, 16 V,+/- 10%, X7R, 0603", Cap_Case=0603, Manufacturer=MuRata, TempCo=X7R, Tolerance_%=10, Value2=16V, ValueDisplayed=4.7µF
FID1 FID2 FID3 FID4 FID5 FID6: "Fiducial mark.  There is nothing to buy or mount.", Manufacturer=N/A
J1: "Connector, HF, 50 Ohm, TH", Color=Waterblue, Manufacturer=Rosenberger
L1 L2 L7 L8 L9: "Ferrite Bead, 1000 ohm @ 100 MHz, 0.35 A, 0402", Manufacturer=MuRata, Supplier Part Number 1=490-5442-1-ND, Value1="0.49 ohm", Value2=0.35A
L3: "Inductor, Wirewound, 4.7 µH, 1.01 A, 0.1 ohm, SMD", Manufacturer="Taiyo Yuden", Supplier Part Number 1=587-1624-1-ND, Value1="0.1 ohm", Value2=1.01A, ValueDisplayed=4.7µH
L4: "Inductor, Wirewound, 100 µH, 0.27 A, 1.4 ohm, SMD", Manufacturer="Taiyo Yuden", Supplier Part Number 1=587-1628-1-ND, Value1="1.4 ohm", Value2=0.27A, ValueDisplayed=100µH
L10: "Inductor, Shielded Drum Core, Metal Composite, 10 µH, 0.125 A, 0.3 ohm, SMD", Manufacturer="Wurth Elektronik", Supplier Part Number 1=732-4516-1-ND, Value1="0.3 ohm", Value2=0.125A, ValueDisplayed=10µH
L11: "Inductor, Shielded Drum Core, Metal Composite, 2.2 µH, 0.5 A, 0.23 ohm, SMD", Manufacturer="Wurth Elektronik", Supplier Part Number 1=732-2953-1-ND, Value1="0.23 ohm", Value2=0.5A, ValueDisplayed=2.2µH
Logo2: library part Pb-Free
Logo3: library part FCC_disclaimer, "FCC_disclaimer"
R1 R2: "RES, 2.00 k, 1%, 0.063 W, 0402", Manufacturer=Vishay-Dale, Power_W=0.063, Supplier Part Number 1=541-2.00KLCT-ND, TempCo="100 ppm/C", Tolerance_%=1, Value1=1%, Value2=0.063W, Value_Code=2k00, ValueDisplayed=2.00k
R3 R6 R20: "RES, 10 k, 5%, 0.063 W, 0402", Manufacturer=Vishay-Dale, Power_W=0.063, Supplier Part Number 1=541-10KJCT-ND, TempCo="200 ppm/C", Tolerance_%=5, Value1=5%, Value2=0.063W, Value_Code=10k0, ValueDisplayed=10k
R4 R5 R7 R8: "RES, 3.3 k, 5%, 0.063 W, 0402", Manufacturer=Vishay-Dale, Power_W=0.063, Supplier Part Number 1=541-3.3KJCT-ND, TempCo="200 ppm/C", Tolerance_%=5, Value1=5%, Value2=0.063W, Value_Code=3k30, ValueDisplayed=3.3k
R9 R11 R17: "RES, 0 ohm, 5%, 0.063W, 0402", Manufacturer=Vishay-Dale, Power_W=0.063, Supplier Part Number 1=541-0.0JCT-ND, TempCo="200 ppm/C", Tolerance_%=5, Value1=5%, Value2=0.063W, Value_Code=0000
R12: "RES, 49.9 ohm, 1%, 0.063W, 0402", Manufacturer=Vishay-Dale, Power_W=0.063, Supplier Part Number 1=541-49.9LCT-ND, TempCo="100 ppm/C", Tolerance_%=1, Value1=1%, Value2=0.063W, Value_Code=49R9
R13: "RES, 33 ohm, 5%, 0.063W, 0402", Manufacturer=Vishay-Dale, Power_W=0.063, Supplier Part Number 1=541-33JCT-ND, TempCo="200 ppm/C", Tolerance_%=5, Value1=5%, Value2=0.063W, Value_Code=33R0
R15 R16: "RES, 10k ohm, 5%, 0.063W, 0402", Manufacturer=Vishay-Dale, Power_W=0.063, Supplier Part Number 1=71-CRCW0402J-10K-E3, TempCo="200 ppm/C", Tolerance_%=5, Value1=5%, Value2=0.063W, Value_Code=10k0
R18: "RES, 4.70 k, 1%, 0.063 W, 0402", Manufacturer="TE Connectivity", Power_W=0.063, Supplier Part Number 1=A121542CT-ND, TempCo="100 ppm/C", Tolerance_%=1, Value1=1%, Value2=0.063W, Value_Code=4k70, ValueDisplayed=4.70k
R21 R25: "RES, 100 k, 1%, 0.063 W, 0402", Manufacturer=Vishay-Dale, Power_W=0.063, Supplier Part Number 1=541-100KLCT-ND, TempCo="100 ppm/C", Tolerance_%=1, Value1=1%, Value2=0.063W, Value_Code=100k
R22: "RES, 82.5 k, 1%, 0.063 W, 0402", Manufacturer=Vishay-Dale, Power_W=0.063, Supplier Part Number 1=541-82.5KLCT-ND, TempCo="100 ppm/C", Tolerance_%=1, Value1=1%, Value2=0.063W, Value_Code=82k5, ValueDisplayed=82.5k
R23: library part CRCW040233k2FKED, "RES, 33.2 k, 1%, 0.063 W, 0402", Manufacturer=Vishay-Dale, Power_W=0.063, Supplier Part Number 1=541-33.2KLCT-ND, TempCo="100 ppm/C", Tolerance_%=1, Value1=1%, Value2=0.063W, Value_Code=33k2, ValueDisplayed=33.2k
U1: "DS90UB913A-Q1/DS90UB914A-Q1 25 to 100 MHz 10/20-Bit FPD-Link III Serializer and Deserializer, RTV0032A", Alternate Manufacturer=None, Manufacturer="Texas Instruments"
U2: library part AS0140, "1MP+ISP Single Package Solution, BGA130", Manufacturer="ON Semiconductor"
U3: "3-V to17-V 0.5-A Step-Down Converters with DCS-Control™, DSG0008A", Alternate Manufacturer="Texas Instruments", Alternate PartNumber=TPS62170QDSGTQ1
U4: "3-V to 17-V, 0.5-A Step-Down Converter with DCS-Control, DSG0008A", Alternate Manufacturer="Texas Instruments", Alternate PartNumber=TPS62171QDSGTQ1
Y1: "OSC, 48MHz, 1.8 to 3.3V, SMD", Frequency=48MHz, Frequency Stability=±10ppm, Manufacturer="Abracon Corporation", Supplier Part Number 1=535-11198-1-ND
ZZ1 ZZ2 ZZ3: library part AssemblyNote, Alternate Manufacturer=-

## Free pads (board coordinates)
  round 62.99 hole 62.99 unplated: MT1(-831.32,-398.5) MT2(32.85,-398.5)
  round 280 hole 280 unplated: ""(-398.25,-1358)

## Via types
v1: diameter 14, hole 6, Layer 1 - Top Layer to Layer 6 - Bottom Layer, tented both sides, 137 vias
v2: diameter 19.68, hole 7.87, Layer 1 - Top Layer to Layer 6 - Bottom Layer, tented both sides, 5 vias
v3: diameter 19.68, hole 7.87, Layer 1 - Top Layer to Layer 6 - Bottom Layer, 4 vias

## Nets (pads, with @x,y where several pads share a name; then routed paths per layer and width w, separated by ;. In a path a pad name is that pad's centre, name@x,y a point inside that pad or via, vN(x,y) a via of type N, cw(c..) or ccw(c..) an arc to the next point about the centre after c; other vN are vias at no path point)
1V8: C8.1 C9.1 C10.1 C18.1 C19.1 C20.1 C25.1 C26.1 C33.1 L7.1 L8.1 L11.2 R6.2 R7.2 R8.2 R15.2 R16.2 U1.11 U1.28 U2.E3 U2.F3 U2.G3 U2.H3 U2.J3 U2.K3 U2.M4 U2.M5 U2.M7 U4.6 | length 1148.5
  Layer 1 - Top Layer w8: U1.11@-463.47,-548.51 -463.47,-529.47 -445,-511 -445,-480.68 C19.1@-442,-477.68 ; C19.1@-443,-483 C19.1@-443,-477.68 ; U4.6@-94.5,-115.44 -94.5,-94
  Layer 1 - Top Layer w10: U1.28@-502.84,-737.49 U1.28@-502,-738.33 ; R15.2@-238.32,-716 -238.31,-677.31 R16.2@-238.31,-676 -210.1,-676 ; -209.7,-675.6 v1(-209.6,-651.8) ; -93.5,-94.4 v1(-87.5,-88.4)
  Layer 1 - Top Layer w13: v1(-502.1,-784) v1@-502.1,-759.1
  Layer 1 - Top Layer w14: v1(-502,-759) U1.28@-502,-738.33
  Layer 1 - Top Layer w15: L8.1@-683.31,-453 L8.1@-683,-453.31
  Layer 1 - Top Layer w18: v1(-719,-417) L8.1@-683.31,-453
  Layer 6 - Bottom Layer w6: v1(-287,-625) -287,-641.5 -278.88,-649.62 R6.2@-261.5,-649.62
  Layer 6 - Bottom Layer w8: C10.1@-449.11,-218.8 C10.1@-448.31,-218
  Layer 6 - Bottom Layer w10: v1@-502,-759.86 v1(-502,-759) ; U2.M4@-475.89,-254.3 U2.M5@-449.11,-254.3 v1(-449.11,-236.55) C10.1@-449.11,-218.8 ; U2.M7@-395,-253.73 v1(-395,-213.5)
  Layer 6 - Bottom Layer w13: v1(-502.1,-784) v1@-502,-759.86
  Layer 6 - Bottom Layer w15: C10.1@-448.31,-218 -448.31,-183 C9.1@-446.31,-181
  Layer 6 - Bottom Layer w24: R7.2@-657,-416.62 -698,-416.87 v1(-719,-417) -750,-448 -750,-659 -668,-741 -564,-741 C25.1@-547,-724 ; C25.1@-547,-723.68 C26.1@-518,-723.68 -502,-739.68 v1(-502,-759)
  other v1: -378.8,-488.1 -677.4,-416.8 -471.5,-307 -234.8,-136.5 -157.9,-136.2 -256.7,-32.3 -204.7,-32.4 -150.4,-32.4
"1V8 EN": R21.1 U3.8 U4.3 | length 477.6
  Layer 1 - Top Layer w6: U4.3@-96.1,-197.3 v1@-76.4,-216 ; v1@-78.2,-215.8 v1@-76.4,-215.8
  Layer 1 - Top Layer w10: U3.8@-133.73,-546.3 -131.8,-544.37 v1(-131.8,-523.4)
  Layer 6 - Bottom Layer w6: R21.1@-201.5,-579.5 -166.9,-544.9 -150.9,-544.9 -131.8,-526.06 v1(-131.8,-523.4) -128.64,-520.24 -128.64,-494.16 -93.5,-459 -93.5,-253.5 -76.5,-236.5 v1@-76.4,-215.8
  other v1: -76.5,-215.9
1V8_VDDCML: C22.1 C23.1 C24.1 L8.2 U1.14 | length 195.6
  Layer 1 - Top Layer w8: C24.1@-568,-498 -553,-498 -522.53,-528.47 U1.14@-522.53,-548.51 ; C24.1@-568,-493 C24.1@-568,-492.68
  Layer 1 - Top Layer w15: L8.2@-680.32,-490 -647.44,-490 C22.1@-643,-485.56 -638.56,-490 -605.68,-490 C23.1@-603,-492.68 C24.1@-568,-492.68
1V8_VDDPLL: C14.1 C15.1 C16.1 L7.2 U1.10 | length 140.9
  Layer 1 - Top Layer w10: U1.10@-443.79,-548.51 -443.79,-532.79 -435,-524 ; -412,-524 -406,-530
  Layer 1 - Top Layer w13: -434,-525 -413,-525
  Layer 1 - Top Layer w15: -407.31,-528.31 -351.31,-528.31 C16.1@-332,-509
2V8: C5.1 C6.1 C7.1 C11.1 C12.1 C13.1 C27.1 C30.1 C35.1 C36.1 L9.1 L10.2 R4.2 R5.2 R21.2 R22.2 R25.2 U2.C10 U2.D10 U2.D11 U2.E11 U2.H10 U2.J10 U2.K10 U2.K12 U2.M6 U3.6 Y1.1 Y1.4 | length 931.3
  Layer 1 - Top Layer w6: R22.2@-44.5,-501.81 v1(-44.5,-481.5)
  Layer 1 - Top Layer w10: R5.2@-348,-777.69 R4.2@-313,-777.69 -305.31,-770 v1(-291,-770) ; U3.6@-94.36,-546.3 -89.59,-541.53 -89.59,-529.59 v1(-89.3,-529.3)
  Layer 1 - Top Layer w21: L9.1@-731.99,-693.4 -732.68,-523 -719,-509.32 v1(-719,-503)
  Layer 3 - Signal w6: v1@-149.96,-563.86 -123.86,-563.86 v1(-89.3,-529.3) -44.5,-484.5 v1(-44.5,-481.5)
  Layer 3 - Signal w10: v1(-151.8,-565.7) v1@-149.96,-563.86
  Layer 4 - Signal 2 w10: v1(-416,-234) -357.5,-234
  Layer 6 - Bottom Layer w6: R21.2@-201.5,-626.19 -151.8,-576.61 v1(-151.8,-565.7)
  Layer 6 - Bottom Layer w10: U2.M6@-422.34,-254.3 -422.34,-240.34 v1(-416,-234) -416,-200.68 C35.1@-399,-183.68 C36.1@-371.68,-211
  Layer 6 - Bottom Layer w14: U2.D11@-287.26,-469.24 v1(-278,-479)
  Layer 6 - Bottom Layer w16: v1(-333,-307.84) U2.K10@-315.26,-307.84 U2.J10@-315.26,-334.61 U2.H10@-315.26,-361.39 ; U2.C10@-315.26,-495.24 U2.D10@-315.26,-468.47 U2.D11@-288.48,-468.47 U2.E11@-288.5,-443.4
  Layer 6 - Bottom Layer w18: C6.1@-217.69,-338 C5.1@-217.69,-268.16
  other v1: -224,-566 -194.3,-518.7 -233,-459 -184,-385.3 -212.7,-362.8 -245.5,-298.9 -207.5,-224.6
"2V8 FB": R22.1 R23.2 U3.5 | length 62
  Layer 1 - Top Layer w6: U3.5@-74.67,-546.3 R22.1@-49.3,-546.3 ; R23.2@-42.5,-579.81 R22.1@-42.5,-543.18
2V8_VDDIO_SER: C28.1 C29.1 L9.2 U1.25 | length 179.8
  Layer 1 - Top Layer w15: -693.31,-743 -658.32,-743 C28.1@-658,-743.32 C29.1@-623,-743.32 -593.32,-743.32 -587.5,-737.5 U1.25@-565,-737.5 ; -692.61,-742.3 L9.2@-692.61,-693.4
"9V IN": L2.2 R9.2 R11.2 | length 39.8
  Layer 1 - Top Layer w10: v1@-301.31,-57.19 v1(-300.5,-58)
  Layer 1 - Top Layer w14: v1(-300.5,-58) v1(-283,-58)
  Layer 1 - Top Layer w16: v1@-301.31,-57.19 L2.2@-301.31,-36
  other v1: -243.5,-220.5 -243.5,-203
CAM_SCL: R5.1 U1.4 U2.B3 | length 506
  Layer 1 - Top Layer w6: U1.4@-398.51,-652.84 -363.16,-652.84 -343,-673 -343,-698
  Layer 1 - Top Layer w8: R5.1@-348,-738.32 -348,-703 -343,-698
  Layer 1 - Top Layer w10: v1@-380.5,-760 -370,-760 R5.1@-348,-738.32
  Layer 3 - Signal w5: v1(-516.04,-508.63) -464,-561 -464,-652 -409,-707 -409,-740 -388.5,-760.5 v1(-378.7,-760.5)
  Layer 6 - Bottom Layer w8: v1(-516.04,-508.63) U2.B3@-502.66,-522.02
CAM_SDA: R4.1 U1.5 U2.C12 | length 446.1
  Layer 1 - Top Layer w6: U1.5@-398.51,-633.16 -357.84,-633.16 -328,-663 -328,-697
  Layer 1 - Top Layer w8: -328,-697 -313,-712 R4.1@-313,-738.32
  Layer 1 - Top Layer w10: -312,-714 v1(-302,-714)
  Layer 6 - Bottom Layer w6: v1(-302,-714) -265.37,-677.37 -247.05,-677.37 -241.19,-671.51 -241.2,-549.7 -230.9,-539.4 -230.9,-526.1 U2.C12@-261.71,-495.24
D0: U1.19 U2.E2 | length 626.8
  Layer 1 - Top Layer w8: v1(-641,-611) -639,-611 -637,-613 U1.19@-587.49,-613.47
  Layer 3 - Signal w5: v1(-641,-611) -641,-521 -618,-498 -618,-372 -556,-310 -526,-310 -493,-343 v1(-493,-459)
  Layer 6 - Bottom Layer w8: U2.E2@-529.39,-441.61 -512,-459 v1(-493,-459)
D1: U1.20 U2.M10 | length 1242.3
  Layer 1 - Top Layer w8: v1@-613,-633.16 U1.20@-587.49,-633.16
  Layer 3 - Signal w5: -622,-633 -646,-657 -646,-716 -657,-727 -682,-727 -748,-661 -748,-223 -721,-196 -391,-196 -335,-252 -313,-252 v1(-288.5,-227.5) ; -621,-633 v1(-611,-633)
  Layer 6 - Bottom Layer w10: U2.M10@-315.26,-254.3 v1(-288.5,-227.5)
D2: U1.21 U2.L8 | length 907.5
  Layer 1 - Top Layer w8: v1(-663,-675) -645.16,-675 -623,-652.84 U1.21@-587.49,-652.84
  Layer 3 - Signal w5: v1(-663,-675) -682,-675 -703,-654 -703,-552 -638,-487 -638,-304 -550.5,-216.5 -448.5,-216.5 -431.01,-233.99 -431,-281.5 ; -431,-282 -405,-308 v1(-367,-308)
  Layer 6 - Bottom Layer w8: U2.L8@-368.8,-281.07 v1@-368.5,-305.5
D3: U1.22 U2.E12 | length 890.9
  Layer 1 - Top Layer w8: U1.22@-595,-673 v1@-569.49,-673
  Layer 3 - Signal w5: v1(-231,-407) -217,-421 -217,-494.5 -257.5,-535 -257.5,-624.5 -211,-671 v1(-211,-711)
  Layer 6 - Bottom Layer w5: v1(-569,-673) -567,-671 -567,-637.76 -552.4,-623.16 -484.78,-623.16 -473.16,-634.78 -473.16,-641.88 -426.04,-689 -411.96,-689 -398.17,-675.21 -355.96,-675.21 -319,-712.17 -319,-721.04 -309.04,-731 -294.96,-731 -274.96,-711 v1(-211,-711) ; U2.E12@-261.4,-442.01 -231,-412 v1(-231,-407)
D4: U1.23 U2.L10 | length 966.1
  Layer 1 - Top Layer w8: -623,-692 U1.23@-587.49,-692.21
  Layer 1 - Top Layer w10: v1(-663,-712) -643,-692 -623,-692
  Layer 3 - Signal w5: v1(-663,-712) -682,-712 -717,-677 -717,-522 -648,-453 -648,-299 -555.3,-206.4 -433.4,-206.4 -420.3,-219.5 -409.99,-219.5 -401.5,-227.99 -401.5,-238.3 -392.3,-247.5 -366.5,-247.5 -342,-272 v1(-325,-272)
  Layer 6 - Bottom Layer w8: v1(-325,-272) U2.L10@-316.39,-281.39
D5: U1.24 U2.L3 | length 679
  Layer 1 - Top Layer w8: v1@-613,-711.9 U1.24@-587.49,-711.9
  Layer 3 - Signal w5: v1(-611,-713) -636,-688 -636,-662 -622,-648 -604,-648 -595,-639 -595,-627 -604,-618 -623,-618 -631,-626 -649,-626 -658,-617 -658,-523 -628,-493 -628,-367 -561,-300 -521,-300 v1(-492,-270.5)
  Layer 6 - Bottom Layer w8: U2.L3@-502.66,-281.07 v1@-490.5,-268.76
D6: U1.26 U2.D2 | length 824.2
  Layer 1 - Top Layer w8: v1(-575,-765) -545.96,-765 -542.21,-761.26 U1.26@-542.21,-737.49
  Layer 3 - Signal w5: v1(-575,-765) -575,-728 -616,-687 -621,-687 -626,-682 -626,-667 -617,-658 -595,-658 -585,-648 -585,-622 -627,-580 -627,-526 -588,-487 -588,-357 -551,-320 -531,-320 -516,-335 -516,-455 v1@-543,-482
  Layer 6 - Bottom Layer w8: v1(-542.67,-481.67) U2.D2@-529.29,-468.29
D7: U1.27 U2.M9 | length 1260.2
  Layer 1 - Top Layer w8: v1(-532,-774) -522.63,-764.63 U1.27@-522.53,-737.49
  Layer 3 - Signal w5: v1(-532,-774) -540,-782 -580,-782 -624,-738 -686,-738 -758,-666 -758,-210 -734,-186 -363,-186 v1(-360,-189)
  Layer 6 - Bottom Layer w5: v1(-360,-189) -350,-189 -341,-198 U2.M9@-341,-252.5
D8: U1.29 U2.D12 | length 580.2
  Layer 1 - Top Layer w8: v1@-483.16,-771.26 U1.29@-483.16,-737.49
  Layer 3 - Signal w5: v1(-483,-774) -472,-785 -285,-785 -268.8,-768.8 -268.8,-524.8 v1(-239,-495)
  Layer 6 - Bottom Layer w8: U2.D12@-261.71,-468.47 v1@-238,-494
D9: U1.30 U2.J2 | length 463.4
  Layer 1 - Top Layer w8: U1.30@-464,-740.77 v1(-464,-717)
  Layer 3 - Signal w5: v1@-541,-347 -568,-374 -568,-493 -511,-550 -511,-651 -464,-698 v1(-464,-717)
  Layer 6 - Bottom Layer w8: v1(-541,-346) U2.J2@-529.61,-335.61
D10: U1.31 U2.H2 | length 606.3
  Layer 1 - Top Layer w8: v1(-444,-759) U1.31@-443.79,-737.49
  Layer 3 - Signal w5: v1(-542,-374) -526,-358 -526,-340 -535,-331 -547,-331 -578,-362 -578,-498 -522,-554 -522,-690 -453,-759 v1(-444,-759)
  Layer 6 - Bottom Layer w8: v1(-542,-374) U2.H2@-529.43,-361.39
D11: U1.32 U2.E1 | length 383
  Layer 1 - Top Layer w8: U1.32@-424.1,-737.49 v1(-424,-713)
  Layer 3 - Signal w5: v1(-545,-431) -558,-444 -558,-488 -475,-571 -475,-662 v1(-424,-713)
  Layer 6 - Bottom Layer w8: U2.E1@-556.61,-441.39 v1(-545,-431)
DOUTP: C17.1 J1.1 L1.1 | length 388.7
  Layer 1 - Top Layer w20: J1.1@-678,-118 -588,-208 -588,-260.84 L1.1@-566.92,-281.92 -513,-335.84 ; C17.1@-513.3,-437.5 -513.3,-335.02
FRAME_SYNC: U1.16 U2.B8 | length 685.9
  Layer 1 - Top Layer w10: v1(-575,-552) -565.39,-552 U1.16@-561.9,-548.51
  Layer 3 - Signal w5: v1(-575,-552) -562,-565 -562,-655 -554,-663 -554,-673 -452,-775 -372,-775 -347,-750 -347,-685.8 -384,-648.8 -384,-522 v1(-368,-506)
  Layer 6 - Bottom Layer w8: U2.B8@-368.8,-522.02 -368.8,-511.2 v1(-368,-506)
